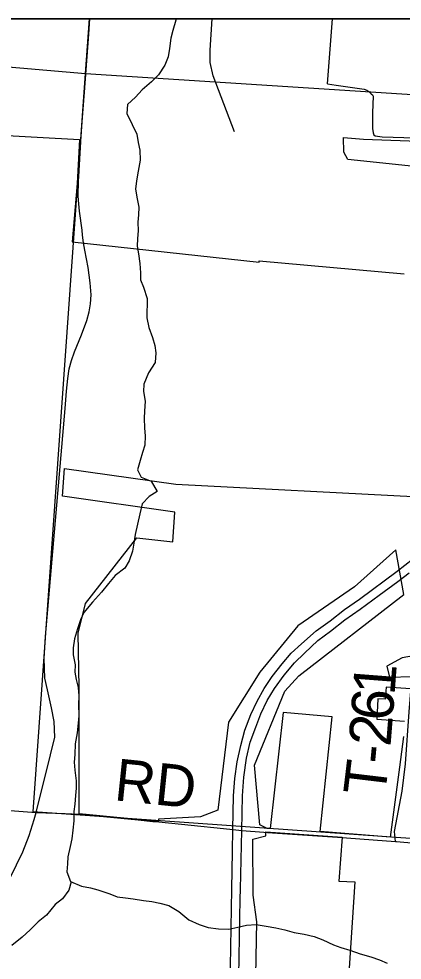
# Model space of a CAD drawing. Extents: x 0 to 34, y 0 to 22.
# Drawn here: x 6.01 to 6.529, y 19.626 to 20.9 of the extents above; entities that cross this region are included whole.
import ezdxf

# ---------------------------------------------------------------- set-up
doc = ezdxf.new("R2010")
doc.units = 0
for name, color, linetype in [('GM_X_City_Street', 7, 'Continuous'), ('GM_X_Corporation', 7, 'Continuous'), ('GM_X_Minor_River', 7, 'Continuous'), ('GM_X_State_Route', 7, 'Continuous'), ('GM_X_Township_Road', 7, 'Continuous'), ('GM_X_Township_Road_Text', 7, 'Continuous'), ('SH_Data', 7, 'Continuous')]:
    doc.layers.add(name, color=color, linetype=linetype)

msp = doc.modelspace()

# ---------------------------------------------------------------- linework, layer by layer
at = {"layer": 'GM_X_City_Street'}
msp.add_line((6.4277, 20.812), (6.4345, 20.9), dxfattribs=at)
for points in [[(6.3021, 20.7472), (6.2734, 20.8229), (6.2692, 20.8407), (6.269, 20.8577), (6.2717, 20.9)], [(6.4277, 20.812), (6.4393, 20.8101), (6.4742, 20.8054), (6.4775, 20.8049), (6.4808, 20.8034), (6.4838, 20.8015), (6.487, 20.7985), (6.4887, 20.7969), (6.4895, 20.7953), (6.4885, 20.7729), (6.4887, 20.7517), (6.4896, 20.7457), (6.4906, 20.743), (6.4921, 20.7414), (6.5016, 20.7401), (6.6046, 20.7373)]]:
    msp.add_lwpolyline(points, dxfattribs=at)
at = {"layer": 'GM_X_Corporation'}
for points in [[(7.5423, 20.9), (5.1364, 20.9)], [(5.7817, 20.7539), (6.0926, 20.7368), (6.0894, 20.6769), (6.0827, 20.5981), (6.3353, 20.5706), (6.3355, 20.5726), (6.5315, 20.5547)], [(6.5538, 20.699), (6.4551, 20.7098), (6.4497, 20.7196), (6.4495, 20.7393), (6.4765, 20.737), (6.6744, 20.73)], [(6.5306, 19.9284), (6.5253, 19.8869), (6.5125, 19.7924), (6.4178, 19.7998), (6.4339, 19.9553), (6.3678, 19.9609), (6.3504, 19.8042), (6.3464, 19.8042), (6.3365, 19.8089), (6.3292, 19.8896), (6.37, 19.9901), (6.389, 20.0105), (6.5312, 20.1207), (6.5201, 20.1813), (6.4645, 20.1313), (6.3876, 20.0785), (6.3364, 20.0156), (6.2939, 19.9482), (6.2797, 19.829), (6.2562, 19.8197), (6.1993, 19.8165), (6.1993, 19.8135), (6.1666, 19.8165), (6.0919, 19.824), (6.0919, 19.8698), (6.0919, 19.9948), (6.0906, 20.0683), (6.1006, 20.1086), (6.17, 20.1974), (6.2188, 20.1922), (6.2216, 20.2323), (6.0694, 20.2537), (6.0721, 20.2915), (6.2227, 20.2703), (6.552, 20.253)], [(6.5442, 20.0378), (6.5286, 20.0351), (6.508, 20.0237), (6.5118, 20.009), (6.5419, 20.0099)], [(6.5405, 19.9931), (6.5071, 19.9954), (6.5057, 19.9791), (6.4959, 19.9794), (6.4943, 19.9519), (6.532, 19.9492)]]:
    msp.add_lwpolyline(points, dxfattribs=at)
for points in [[(6.106, 20.9), (5.2435, 20.9), (6.1004, 20.8259)], [(7.1529, 20.9), (6.106, 20.9), (6.1004, 20.8259), (7.1451, 20.7589)], [(6.1004, 20.8259), (7.1451, 20.7589), (7.0904, 19.7521), (6.9862, 19.7588), (6.0298, 19.8267)], [(6.3445, 19.7994), (6.4475, 19.7921), (6.4432, 19.7329), (6.4647, 19.7318), (6.4572, 19.6149), (6.4322, 19.2814), (6.3195, 19.2898), (6.3221, 19.331), (6.3247, 19.4839), (6.3294, 19.5324), (6.3322, 19.6775), (6.3272, 19.7138), (6.3267, 19.7897), (6.3445, 19.7941)]]:
    msp.add_lwpolyline(points, close=True, dxfattribs=at)
at = {"layer": 'GM_X_Minor_River'}
for points in [[(6.2232, 20.9), (6.2227, 20.8981), (6.2185, 20.8844), (6.2161, 20.8738), (6.2141, 20.8598), (6.2122, 20.8485), (6.2079, 20.8375), (6.1995, 20.8243), (6.19, 20.8149), (6.1774, 20.8039), (6.1683, 20.7938), (6.1572, 20.784), (6.1564, 20.7719), (6.1635, 20.757), (6.1698, 20.7437), (6.172, 20.7327), (6.1742, 20.7221), (6.1745, 20.7088), (6.1718, 20.694)], [(6.1718, 20.694), (6.1694, 20.6807), (6.1682, 20.6694), (6.1704, 20.6565), (6.1726, 20.6451), (6.1721, 20.6348), (6.1713, 20.6246), (6.1716, 20.6132), (6.1711, 20.6026), (6.1703, 20.5924), (6.1721, 20.5821), (6.1739, 20.5688), (6.175, 20.5563), (6.1749, 20.5465), (6.179, 20.537), (6.1838, 20.5214), (6.1837, 20.4952), (6.1862, 20.4823), (6.1914, 20.4686), (6.1944, 20.4576), (6.1955, 20.4481), (6.195, 20.4348), (6.1858, 20.4209), (6.1793, 20.4057), (6.1792, 20.3955), (6.1814, 20.3826), (6.1805, 20.3689), (6.1797, 20.3595), (6.1804, 20.3458), (6.1811, 20.3356), (6.1806, 20.323), (6.1775, 20.3128), (6.1744, 20.3022), (6.1709, 20.2897), (6.1758, 20.2795), (6.1893, 20.2744), (6.1976, 20.26), (6.1869, 20.2536), (6.177, 20.2434), (6.1739, 20.2298), (6.1677, 20.2018), (6.1661, 20.1904), (6.1641, 20.1794), (6.1595, 20.1662), (6.1537, 20.1564), (6.1408, 20.1466), (6.1316, 20.1356), (6.1221, 20.124), (6.1099, 20.1104), (6.0985, 20.0964), (6.0938, 20.0866), (6.0896, 20.0741), (6.0857, 20.0609), (6.0841, 20.0484), (6.0841, 20.0389), (6.0866, 20.0256), (6.0862, 20.0157), (6.088, 20.0059), (6.0906, 19.9948), (6.0916, 19.9838), (6.0912, 19.9721), (6.0914, 19.9565), (6.0906, 19.9467), (6.0894, 19.9334), (6.0866, 19.9186), (6.0862, 19.9042), (6.0853, 19.894), (6.086, 19.883), (6.0882, 19.8686), (6.0881, 19.8587), (6.0873, 19.8488), (6.0861, 19.8371), (6.0849, 19.8272), (6.0848, 19.8143), (6.0836, 19.8018), (6.082, 19.7901), (6.08, 19.7795), (6.0769, 19.7659), (6.0761, 19.7564), (6.0753, 19.7454), (6.0805, 19.7321), (6.0952, 19.7259), (6.1073, 19.7236), (6.1175, 19.7212), (6.1333, 19.7154), (6.1435, 19.7116), (6.1545, 19.71), (6.1651, 19.7088), (6.179, 19.7068), (6.1904, 19.7052), (6.201, 19.7032), (6.2134, 19.6997), (6.2266, 19.6917), (6.2402, 19.6802), (6.2545, 19.674), (6.2666, 19.6701), (6.2802, 19.6682), (6.2946, 19.6677), (6.3067, 19.6706), (6.3185, 19.6732), (6.3313, 19.6739)], [(6.0812, 19.7318), (6.0781, 19.7207), (6.0697, 19.709), (6.0598, 19.7011), (6.048, 19.6868), (6.0366, 19.6778), (6.0259, 19.6668), (6.0149, 19.657), (6.0012, 19.6458)], [(6.3313, 19.6739), (6.3449, 19.6719), (6.3578, 19.6695), (6.3699, 19.6668), (6.3827, 19.6633), (6.3963, 19.6609), (6.4099, 19.6578), (6.4216, 19.6532), (6.436, 19.6466), (6.4458, 19.6428), (6.4579, 19.6393), (6.4718, 19.6343), (6.4865, 19.6304), (6.4982, 19.6265), (6.5084, 19.6219)]]:
    msp.add_lwpolyline(points, dxfattribs=at)
at = {"layer": 'GM_X_State_Route'}
for p, q in [((6.0953, 20.7477), (6.0967, 20.7664)), ((6.0953, 20.7467), (6.0953, 20.7477)), ((6.031, 19.8162), (6.0338, 19.8257)), ((6.3101, 19.7218), (6.3119, 19.8015))]:
    msp.add_line(p, q, dxfattribs=at)
for points in [[(6.0967, 20.7664), (6.0992, 20.8009), (6.1049, 20.8792), (6.1065, 20.9)], [(6.0915, 20.6866), (6.0949, 20.7418), (6.0953, 20.7467)], [(6.0996, 20.5869), (6.0978, 20.5967), (6.0966, 20.6072), (6.0959, 20.6139), (6.0927, 20.6397), (6.0917, 20.6495), (6.0908, 20.6599), (6.0912, 20.6806), (6.0915, 20.6866)], [(6.0338, 19.8257), (6.0535, 19.9036), (6.0592, 19.9278), (6.0584, 19.9491), (6.0547, 19.9676), (6.0494, 19.9919), (6.0458, 20.0075), (6.0445, 20.0341), (6.0463, 20.0639), (6.0733, 20.3725), (6.0749, 20.3962), (6.0769, 20.4133), (6.0787, 20.4263), (6.0815, 20.4374), (6.0856, 20.4491), (6.095, 20.4723), (6.1025, 20.4917), (6.1055, 20.5032), (6.1075, 20.5142), (6.1083, 20.5266), (6.1071, 20.5427), (6.1042, 20.5634), (6.0996, 20.5869)], [(6.2998, 19.8028), (6.3009, 19.8483), (6.3023, 19.8717), (6.3057, 19.8944), (6.3105, 19.9164), (6.3159, 19.9371), (6.3241, 19.9583), (6.3325, 19.9763), (6.3422, 19.9937), (6.3531, 20.0097), (6.3666, 20.0271), (6.3787, 20.0412), (6.3927, 20.0542), (6.4125, 20.0714), (6.4312, 20.0853), (6.451, 20.1003), (6.471, 20.1146), (6.5219, 20.1524), (6.5429, 20.1684)], [(6.4977, 20.12), (6.5228, 20.1384), (6.5381, 20.1501)], [(6.3119, 19.8015), (6.3127, 19.8484), (6.3147, 19.8737), (6.3185, 19.8992), (6.3234, 19.9208), (6.3307, 19.9413), (6.3376, 19.9594), (6.346, 19.9774), (6.3563, 19.9935), (6.3692, 20.0117), (6.383, 20.0282), (6.3965, 20.0415), (6.4149, 20.0583), (6.4317, 20.071), (6.4514, 20.0864), (6.4718, 20.1009), (6.4977, 20.12)], [(5.9907, 19.7204), (6.0158, 19.7726), (6.0245, 19.7944), (6.031, 19.8162)], [(6.2983, 19.722), (6.2995, 19.7728), (6.2998, 19.8028)], [(5.8362, 18.917), (6.0272, 18.9618), (6.051, 18.9673), (6.0705, 18.9719), (6.0867, 18.9761), (6.1046, 18.9812), (6.1203, 18.9873), (6.1417, 18.9969), (6.1689, 19.0124), (6.1924, 19.03), (6.2093, 19.0452), (6.2198, 19.0567), (6.2394, 19.0808), (6.2587, 19.1117), (6.2708, 19.1398), (6.2792, 19.1668), (6.2843, 19.1903), (6.287, 19.2128), (6.2886, 19.237), (6.2901, 19.2864), (6.2912, 19.3592), (6.2935, 19.4826), (6.2965, 19.6173), (6.2983, 19.722)], [(6.0574, 18.9556), (6.0582, 18.9558), (6.0984, 18.9669), (6.1344, 18.9804), (6.1637, 18.9953), (6.1936, 19.0153), (6.2203, 19.0394), (6.2434, 19.0671), (6.2621, 19.0935), (6.2775, 19.1245), (6.2879, 19.1536), (6.2947, 19.1801), (6.2983, 19.2065), (6.3004, 19.2337), (6.3012, 19.272), (6.3027, 19.3432), (6.3052, 19.4673), (6.3081, 19.6043), (6.3098, 19.7089), (6.3101, 19.7218)]]:
    msp.add_lwpolyline(points, dxfattribs=at)
at = {"layer": 'GM_X_Township_Road'}
for p, q in [((6.0338, 19.8257), (6.0733, 19.8242)), ((6.172, 19.8157), (6.1917, 19.8137))]:
    msp.add_line(p, q, dxfattribs=at)
for points in [[(6.5199, 19.7865), (6.5185, 19.7999), (6.5286, 19.8546), (6.5333, 19.8918), (6.5381, 19.9618), (6.5418, 20.0066)], [(5.3944, 19.8788), (5.4816, 19.8694), (5.5092, 19.8667), (5.7096, 19.8503), (5.9222, 19.8343), (6.0338, 19.8257)], [(6.0733, 19.8242), (6.0921, 19.8235), (6.172, 19.8157)], [(6.1917, 19.8137), (6.1996, 19.813), (6.2871, 19.8039), (6.2998, 19.8028), (6.3119, 19.8015), (6.3418, 19.7991)], [(6.3418, 19.7991), (6.3467, 19.7987), (6.4413, 19.7921)], [(6.4413, 19.7921), (6.5199, 19.7865), (6.5209, 19.7864)], [(6.5209, 19.7864), (6.6067, 19.7786), (6.7488, 19.7702), (6.9834, 19.759), (7.0732, 19.7546), (7.2824, 19.7367), (7.33, 19.7319), (7.4965, 19.7186)]]:
    msp.add_lwpolyline(points, dxfattribs=at)
at = {"layer": 'SH_Data'}
msp.add_line((2.1, 20.9), (8.9, 20.9), dxfattribs=at)

# ---------------------------------------------------------------- texts
at = {"layer": 'GM_X_Township_Road_Text'}
for s, height, rotation, p in [('1', 0.0568, 85.568, (6.5183, 19.9835)), ('6', 0.0568, 85.5637, (6.5156, 19.9488)), ('2', 0.0568, 85.4371, (6.5129, 19.9141)), ('-', 0.0568, 84.5657, (6.5106, 19.8901)), ('RD', 0.05682, 354.0783, (6.1381, 19.8424)), ('T', 0.0568, 83.1828, (6.5054, 19.8465))]:
    msp.add_text(s, height=height, rotation=rotation, dxfattribs=at).set_placement(p)

doc.saveas('drawing.dxf')
